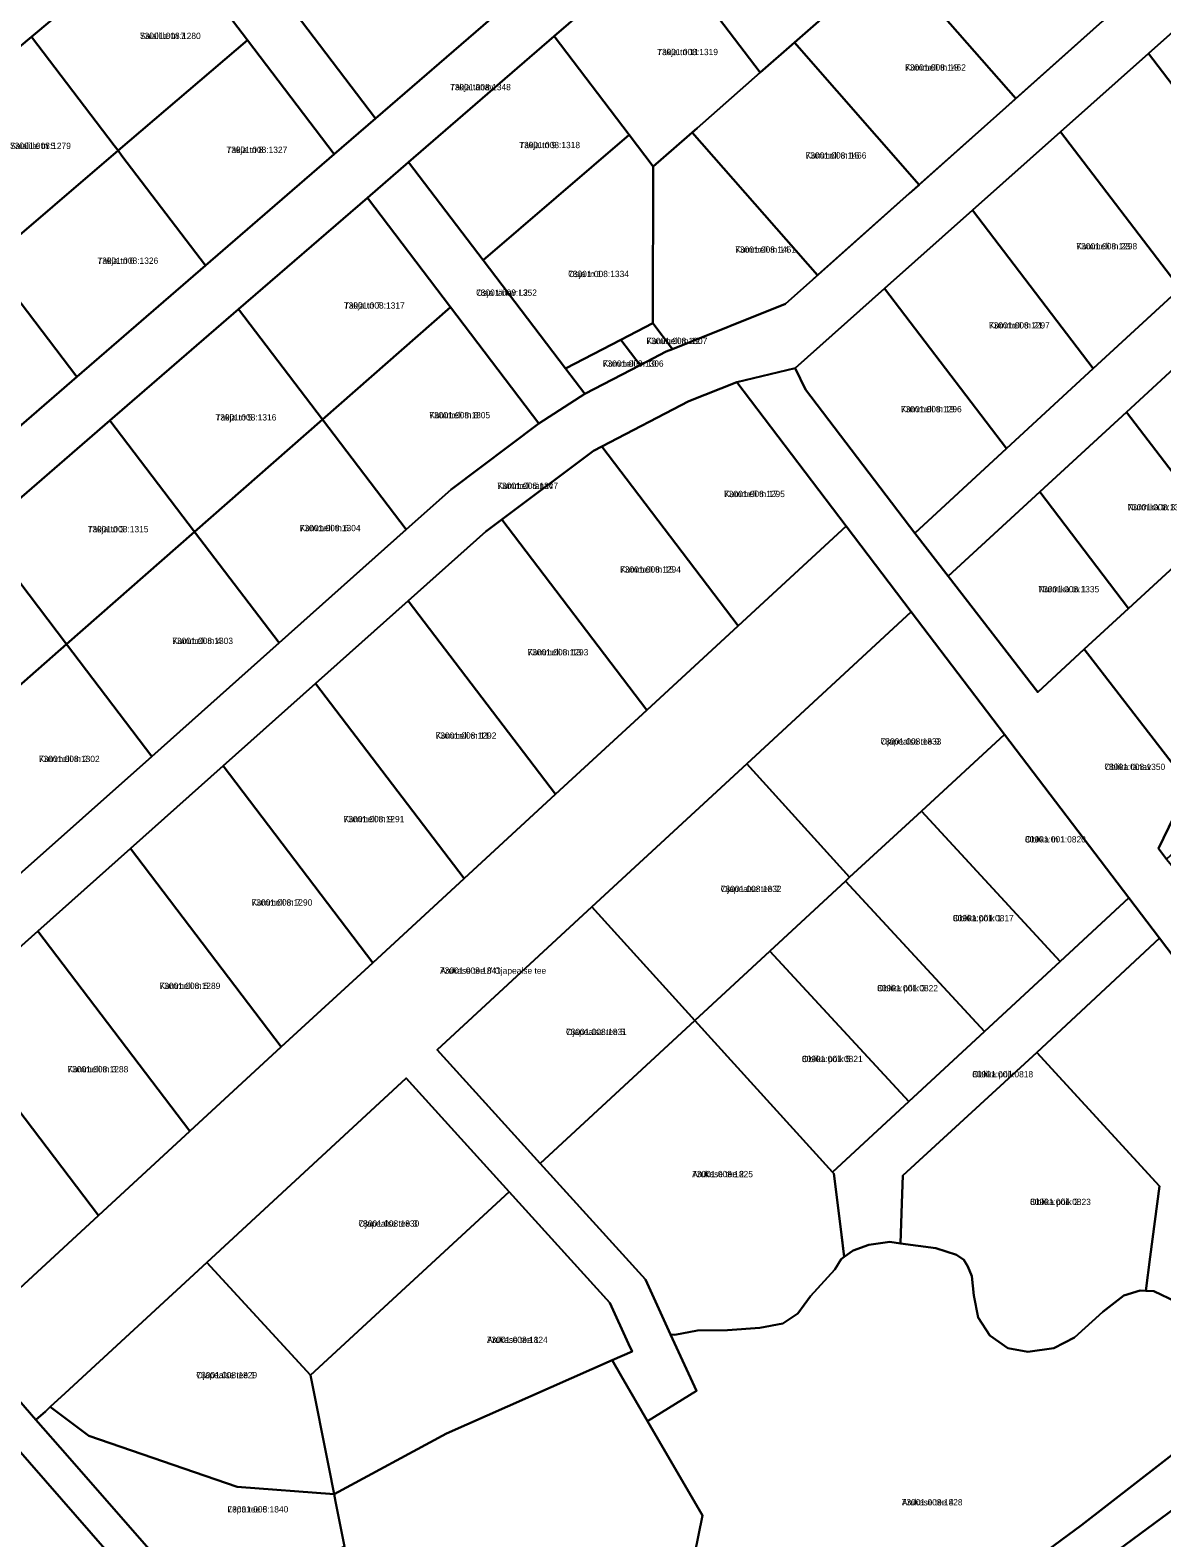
# Model space of a CAD drawing. Extents: x 524000 to 564260, y 6469338 to 6496391.
# Drawn here: x 535130.7 to 535400.5, y 6472024.8 to 6472384.2 of the extents above; entities that cross this region are included whole.
import ezdxf

# ---------------------------------------------------------------- set-up
doc = ezdxf.new("R2010")
doc.units = 0
for name, color, linetype in [('L_AADRESS', 7, 'Continuous'), ('PIIR', 7, 'Continuous'), ('TUNNUS', 7, 'Continuous')]:
    doc.layers.add(name, color=color, linetype=linetype)

msp = doc.modelspace()

# ---------------------------------------------------------------- linework, layer by layer
at = {"layer": 'PIIR'}
for points in [[(535113.22, 6472384.72), (535140.09, 6472407.24), (535166.96, 6472429.76), (535193.81, 6472452.26), (535220.65, 6472474.76), (535247.5, 6472497.26), (535274.37, 6472519.79), (535301.22, 6472542.29), (535326.58, 6472563.55), (535328.07, 6472564.8), (535335.94, 6472554.46), (535334.43, 6472553.19), (535308.7, 6472531.62), (535281.47, 6472508.79), (535254.23, 6472485.96), (535227, 6472463.13), (535199.76, 6472440.29), (535172.02, 6472417.04), (535162.04, 6472408.68), (535130.96, 6472382.62), (535099.89, 6472356.58)], [(535111.09, 6472274.99), (535141.78, 6472301.52), (535172.48, 6472328.06), (535203.18, 6472354.6), (535213.03, 6472363.12), (535240.43, 6472386.81), (535267.35, 6472410.08), (535294.25, 6472433.34), (535321.16, 6472456.61), (535348.06, 6472479.87), (535373.41, 6472501.79), (535374.98, 6472503.14), (535382.87, 6472492.75), (535381.32, 6472491.41), (535357.47, 6472470.79), (535332.08, 6472448.84), (535306.68, 6472426.89), (535281.29, 6472404.93), (535255.59, 6472382.72), (535220.92, 6472352.74), (535211.07, 6472344.22), (535180.37, 6472317.68), (535149.67, 6472291.14), (535118.97, 6472264.6)], [(535418.29, 6472397.33), (535397.32, 6472378.65), (535376.36, 6472359.97), (535355.39, 6472341.29), (535334.42, 6472322.61), (535313.08, 6472303.59), (535299.14, 6472300.3), (535287.77, 6472295.76), (535266.99, 6472284.97), (535264.96, 6472283.92), (535243.16, 6472267.54), (535239.34, 6472264.68), (535220.83, 6472248.19), (535198.74, 6472228.5), (535176.65, 6472208.82), (535154.56, 6472189.13), (535132.47, 6472169.45), (535110.37, 6472149.76)], [(535126.6, 6472181.63), (535159.68, 6472211.1), (535190.01, 6472238.12), (535220.33, 6472265.14), (535231.06, 6472274.71), (535251.99, 6472290.43), (535262.93, 6472297.51), (535276.1, 6472304.34), (535282.35, 6472307.59), (535283.86, 6472308.19), (535310.79, 6472318.97), (535317.21, 6472324.69), (535340.28, 6472345.24), (535363.35, 6472365.79), (535386.41, 6472386.34)], [(535115.53, 6472072.75), (535146.96, 6472101.69), (535168.76, 6472121.76), (535190.55, 6472141.83), (535212.34, 6472161.91), (535234.14, 6472181.99), (535255.93, 6472202.06), (535277.72, 6472222.14), (535299.52, 6472242.22), (535325.27, 6472265.94), (535340.78, 6472245.55), (535301.53, 6472209.33), (535264.61, 6472175.25), (535227.69, 6472141.17), (535252.24, 6472114.09), (535277.37, 6472086.38), (535283.37, 6472073.31), (535289.52, 6472059.91), (535277.89, 6472052.62), (535271.58, 6472063.44), (535269.41, 6472067.16), (535274.21, 6472069.28), (535273.38, 6472071.09), (535268.92, 6472080.81), (535244.89, 6472107.31), (535220.34, 6472134.39), (535172.76, 6472090.47), (535139.01, 6472059.32), (535135.47, 6472056.05), (535134.31, 6472054.98), (535132.04, 6472052.94), (535118.83, 6472068.12)], [(535298.79, 6471954.5), (535478.29, 6472086.95), (535613.88, 6472188.1), (535624.16, 6472196.1), (535638.82, 6472207.03)], [(535285.35, 6472002.41), (535291.02, 6472030.12), (535277.89, 6472052.62), (535289.52, 6472059.91), (535283.37, 6472073.31), (535284.36, 6472073.21), (535289.76, 6472074.27), (535296.97, 6472074.33), (535304.64, 6472074.88), (535310.14, 6472075.94), (535313.72, 6472078.29), (535316.72, 6472082.42), (535322.53, 6472088.76), (535324.03, 6472091.26), (535324.8, 6472091.83), (535326.89, 6472093.32), (535330.65, 6472094.67), (535335.69, 6472095.35), (535338.2, 6472095.02), (535346.67, 6472093.89), (535351.57, 6472092.26), (535353.32, 6472091.08), (535354.3, 6472089.52), (535355.2, 6472087.19), (535355.66, 6472082.59), (535356.7, 6472077.32), (535359.47, 6472073.09), (535363.77, 6472070.05), (535368.54, 6472069.19), (535374.75, 6472070.05), (535379.71, 6472072.57), (535386.46, 6472078.72), (535391.48, 6472082.56), (535395.32, 6472083.75), (535396.67, 6472083.7), (535398.63, 6472083.62), (535403.92, 6472081.11)], [(535412.98, 6472052.43), (535381.36, 6472027.86), (535302.63, 6471969.76)]]:
    msp.add_lwpolyline(points, dxfattribs=at)
for points in [[(535281.29, 6472404.93), (535306.68, 6472426.89), (535330, 6472396.23), (535312.9, 6472381.22), (535304.76, 6472374.07)], [(535336.11, 6472401.59), (535355.24, 6472418.39), (535359.31, 6472421.96), (535388.75, 6472388.43), (535386.41, 6472386.34), (535365.7, 6472367.89)], [(535203.18, 6472354.6), (535182.48, 6472381.81), (535162.04, 6472408.68), (535172.02, 6472417.04), (535192.07, 6472390.68), (535192.98, 6472389.48), (535193.89, 6472388.28), (535213.03, 6472363.12)], [(535192.98, 6472389.48), (535220.55, 6472412.95), (535221.46, 6472411.76), (535240.43, 6472386.81), (535213.03, 6472363.12), (535193.89, 6472388.28)], [(535130.96, 6472382.62), (535162.04, 6472408.68), (535182.48, 6472381.81), (535151.62, 6472355.47), (535150.71, 6472356.67)], [(535255.59, 6472382.72), (535281.29, 6472404.93), (535304.76, 6472374.07), (535289.7, 6472360.85), (535279.22, 6472351.65), (535273.48, 6472359.2)], [(535312.9, 6472381.22), (535330, 6472396.23), (535336.11, 6472401.59), (535365.7, 6472367.89), (535363.35, 6472365.79), (535342.64, 6472347.34)], [(535397.32, 6472378.65), (535418.29, 6472397.33), (535446.24, 6472360.71), (535425.56, 6472341.66)], [(535099.89, 6472356.58), (535130.96, 6472382.62), (535150.71, 6472356.67), (535151.62, 6472355.47), (535120.78, 6472329.12), (535119.86, 6472330.33)], [(535151.62, 6472355.47), (535182.48, 6472381.81), (535203.18, 6472354.6), (535172.48, 6472328.06), (535152.53, 6472354.27)], [(535220.92, 6472352.74), (535255.59, 6472382.72), (535273.48, 6472359.2), (535238.68, 6472329.4)], [(535288.5, 6472359.8), (535289.7, 6472360.85), (535304.76, 6472374.07), (535312.9, 6472381.22), (535342.64, 6472347.34), (535340.28, 6472345.24), (535318.4, 6472325.75)], [(535341.6, 6472264.32), (535363.5, 6472284.49), (535384.18, 6472303.54), (535404.88, 6472322.61), (535425.56, 6472341.66), (535446.24, 6472360.71), (535466.53, 6472379.4), (535468.03, 6472380.78), (535475.91, 6472370.37), (535474.45, 6472369.02), (535454.15, 6472350.33), (535433.47, 6472331.28), (535412.79, 6472312.23), (535392.1, 6472293.17), (535371.42, 6472274.12), (535349.61, 6472254.03)], [(535376.36, 6472359.97), (535397.32, 6472378.65), (535425.56, 6472341.66), (535404.88, 6472322.61)], [(535238.68, 6472329.4), (535273.48, 6472359.2), (535279.22, 6472351.65), (535279.16, 6472314.37), (535271.49, 6472310.4), (535258.32, 6472303.57)], [(535279.22, 6472351.65), (535288.5, 6472359.8), (535318.4, 6472325.75), (535317.21, 6472324.69), (535310.79, 6472318.97), (535283.86, 6472308.19), (535279.16, 6472314.37)], [(535355.39, 6472341.29), (535376.36, 6472359.97), (535404.88, 6472322.61), (535384.18, 6472303.54)], [(535120.78, 6472329.12), (535151.62, 6472355.47), (535152.53, 6472354.27), (535172.48, 6472328.06), (535141.78, 6472301.52), (535121.68, 6472327.93)], [(535251.99, 6472290.43), (535230.87, 6472318.2), (535211.07, 6472344.22), (535220.92, 6472352.74), (535238.68, 6472329.4), (535258.32, 6472303.57), (535262.93, 6472297.51)], [(535180.37, 6472317.68), (535211.07, 6472344.22), (535230.87, 6472318.2), (535200.35, 6472291.41)], [(535334.42, 6472322.61), (535355.39, 6472341.29), (535384.18, 6472303.54), (535363.5, 6472284.49)], [(535089.93, 6472302.79), (535120.78, 6472329.12), (535121.68, 6472327.93), (535141.78, 6472301.52), (535111.09, 6472274.99), (535090.84, 6472301.6)], [(535313.08, 6472303.59), (535334.42, 6472322.61), (535363.5, 6472284.49), (535341.6, 6472264.32), (535315.57, 6472298.54)], [(535149.67, 6472291.14), (535180.37, 6472317.68), (535200.35, 6472291.41), (535169.84, 6472264.63)], [(535200.35, 6472291.41), (535230.87, 6472318.2), (535251.99, 6472290.43), (535231.06, 6472274.71), (535220.33, 6472265.14)], [(535271.49, 6472310.4), (535279.16, 6472314.37), (535283.86, 6472308.19), (535282.35, 6472307.59), (535276.1, 6472304.34)], [(535392.1, 6472293.17), (535412.79, 6472312.23), (535433.97, 6472284.48), (535413.29, 6472265.39)], [(535258.32, 6472303.57), (535271.49, 6472310.4), (535276.1, 6472304.34), (535262.93, 6472297.51)], [(535266.99, 6472284.97), (535287.77, 6472295.76), (535299.14, 6472300.3), (535325.27, 6472265.94), (535299.52, 6472242.22)], [(535362.97, 6472216.3), (535340.78, 6472245.55), (535325.27, 6472265.94), (535299.14, 6472300.3), (535313.08, 6472303.59), (535315.57, 6472298.54), (535341.6, 6472264.32), (535349.61, 6472254.03), (535370.94, 6472226.42), (535382.02, 6472236.62), (535407.04, 6472204.23), (535399.76, 6472189.17), (535401.66, 6472186.63), (535402.87, 6472185.09), (535412.32, 6472172.76), (535432.95, 6472145.9), (535452.15, 6472120.89), (535442.26, 6472112.1), (535399.94, 6472167.74), (535392.62, 6472177.34)], [(535371.42, 6472274.12), (535392.1, 6472293.17), (535413.29, 6472265.39), (535392.58, 6472246.36)], [(535118.97, 6472264.6), (535149.67, 6472291.14), (535169.84, 6472264.63), (535139.33, 6472237.85)], [(535169.84, 6472264.63), (535200.35, 6472291.41), (535220.33, 6472265.14), (535190.01, 6472238.12)], [(535243.16, 6472267.54), (535264.96, 6472283.92), (535266.99, 6472284.97), (535299.52, 6472242.22), (535277.72, 6472222.14)], [(535433.97, 6472284.48), (535464.51, 6472244.43), (535401.66, 6472186.63), (535399.76, 6472189.17), (535407.04, 6472204.23), (535382.02, 6472236.62), (535392.58, 6472246.36), (535413.29, 6472265.39)], [(535349.61, 6472254.03), (535371.42, 6472274.12), (535392.58, 6472246.36), (535382.02, 6472236.62), (535370.94, 6472226.42)], [(535086.57, 6472236.59), (535118.97, 6472264.6), (535139.33, 6472237.85), (535106.58, 6472209.11)], [(535139.33, 6472237.85), (535169.84, 6472264.63), (535190.01, 6472238.12), (535159.68, 6472211.1)], [(535220.83, 6472248.19), (535239.34, 6472264.68), (535243.16, 6472267.54), (535277.72, 6472222.14), (535255.93, 6472202.06)], [(535198.74, 6472228.5), (535220.83, 6472248.19), (535255.93, 6472202.06), (535234.14, 6472181.99)], [(535301.53, 6472209.33), (535340.78, 6472245.55), (535362.97, 6472216.3), (535343.19, 6472198.03), (535326.04, 6472182.27)], [(535106.58, 6472209.11), (535139.33, 6472237.85), (535159.68, 6472211.1), (535126.6, 6472181.63)], [(535176.65, 6472208.82), (535198.74, 6472228.5), (535234.14, 6472181.99), (535212.34, 6472161.91)], [(535376.32, 6472162.22), (535343.19, 6472198.03), (535362.97, 6472216.3), (535392.62, 6472177.34)], [(535154.56, 6472189.13), (535176.65, 6472208.82), (535212.34, 6472161.91), (535190.55, 6472141.83)], [(535307.05, 6472164.67), (535289.18, 6472148.17), (535264.61, 6472175.25), (535301.53, 6472209.33), (535326.04, 6472182.27), (535325.1, 6472181.37)], [(535358.25, 6472145.52), (535325.1, 6472181.37), (535326.04, 6472182.27), (535343.19, 6472198.03), (535376.32, 6472162.22)], [(535132.47, 6472169.45), (535154.56, 6472189.13), (535190.55, 6472141.83), (535168.76, 6472121.76)], [(535340.2, 6472128.83), (535307.05, 6472164.67), (535325.1, 6472181.37), (535358.25, 6472145.52)], [(535227.69, 6472141.17), (535264.61, 6472175.25), (535289.18, 6472148.17), (535252.24, 6472114.09)], [(535322.28, 6472111.65), (535321.99, 6472111.99), (535340.2, 6472128.83), (535358.25, 6472145.52), (535376.32, 6472162.22), (535392.62, 6472177.34), (535399.94, 6472167.74), (535370.68, 6472140.51), (535338.8, 6472111.19), (535338.55, 6472104.59), (535338.2, 6472095.02), (535335.69, 6472095.35), (535330.65, 6472094.67), (535326.89, 6472093.32), (535324.8, 6472091.83), (535323.8, 6472099.68)], [(535110.37, 6472149.76), (535132.47, 6472169.45), (535168.76, 6472121.76), (535146.96, 6472101.69)], [(535400, 6472108.63), (535370.68, 6472140.51), (535399.94, 6472167.74), (535442.26, 6472112.1), (535455.45, 6472094.81), (535445.91, 6472087.3), (535428.99, 6472069.36), (535423.36, 6472063.39), (535420.71, 6472065.2), (535419.77, 6472066.01), (535415.41, 6472069.78), (535409.37, 6472077.69), (535403.92, 6472081.11), (535398.63, 6472083.62), (535396.67, 6472083.7), (535397.75, 6472091.8)], [(535321.99, 6472111.99), (535289.18, 6472148.17), (535307.05, 6472164.67), (535340.2, 6472128.83)], [(535079.48, 6472122.23), (535110.37, 6472149.76), (535146.96, 6472101.69), (535115.53, 6472072.75), (535103.74, 6472088.93)], [(535322.53, 6472088.76), (535316.72, 6472082.42), (535313.72, 6472078.29), (535310.14, 6472075.94), (535304.64, 6472074.88), (535296.97, 6472074.33), (535289.76, 6472074.27), (535284.36, 6472073.21), (535283.37, 6472073.31), (535277.37, 6472086.38), (535252.24, 6472114.09), (535289.18, 6472148.17), (535321.99, 6472111.99), (535322.28, 6472111.65), (535324.14, 6472097.15), (535324.8, 6472091.83), (535324.03, 6472091.26)], [(535338.55, 6472104.59), (535338.8, 6472111.19), (535370.68, 6472140.51), (535400, 6472108.63), (535397.75, 6472091.8), (535396.67, 6472083.7), (535395.32, 6472083.75), (535391.48, 6472082.56), (535386.46, 6472078.72), (535379.72, 6472072.57), (535374.75, 6472070.05), (535368.54, 6472069.19), (535363.77, 6472070.05), (535359.47, 6472073.09), (535356.7, 6472077.32), (535355.66, 6472082.59), (535355.2, 6472087.19), (535354.3, 6472089.52), (535353.32, 6472091.08), (535351.57, 6472092.26), (535346.67, 6472093.89), (535338.2, 6472095.02)], [(535172.76, 6472090.47), (535220.34, 6472134.39), (535244.89, 6472107.31), (535197.55, 6472063.61)], [(535201.9, 6472041.64), (535197.55, 6472063.61), (535244.89, 6472107.31), (535268.92, 6472080.81), (535273.38, 6472071.09), (535274.21, 6472069.28), (535269.41, 6472067.16), (535229.95, 6472049.72), (535203.16, 6472035.27)], [(535264.68, 6471941.76), (535285.62, 6471957.21), (535302.63, 6471969.76), (535381.36, 6472027.86), (535412.98, 6472052.43), (535417.85, 6472057.58), (535423.36, 6472063.39), (535428.99, 6472069.36), (535445.91, 6472087.3), (535455.45, 6472094.81), (535465.93, 6472103.05), (535469.22, 6472098.73), (535478.29, 6472086.95), (535298.79, 6471954.5), (535270.76, 6471933.77)], [(535135.47, 6472056.05), (535139.01, 6472059.32), (535172.76, 6472090.47), (535197.55, 6472063.61), (535201.9, 6472041.64), (535203.16, 6472035.27), (535180.04, 6472037.01), (535144.69, 6472049.11)], [(535243.25, 6471913.67), (535112.43, 6472063.39), (535118.83, 6472068.12), (535132.04, 6472052.94), (535139.6, 6472044.38), (535173.44, 6472005.7), (535179.55, 6471998.7), (535249.66, 6471918.38)], [(535269.41, 6472067.16), (535271.58, 6472063.44), (535277.89, 6472052.62), (535291.02, 6472030.12), (535285.35, 6472002.41), (535236.46, 6471978.82), (535233.36, 6471976.85), (535204.08, 6472012.54), (535179.55, 6471998.7), (535173.44, 6472005.7), (535205.58, 6472022.79), (535203.5, 6472033.51), (535203.16, 6472035.27), (535229.95, 6472049.72)], [(535066.56, 6471943.12), (535021.96, 6471996.63), (535053.4, 6472019.82), (535110.84, 6472062.22), (535112.43, 6472063.39), (535243.25, 6471913.67), (535148.85, 6471844.29), (535125.57, 6471872.24), (535101.66, 6471900.94)], [(535132.04, 6472052.94), (535134.31, 6472054.98), (535135.47, 6472056.05), (535144.69, 6472049.11), (535180.04, 6472037.01), (535203.16, 6472035.27), (535203.5, 6472033.51), (535205.58, 6472022.79), (535173.44, 6472005.7), (535139.6, 6472044.38)]]:
    msp.add_lwpolyline(points, close=True, dxfattribs=at)

# ---------------------------------------------------------------- texts
at = {"layer": 'L_AADRESS'}
for s, p in [('Saialille tn 7', (535156.83, 6472382.07)), ('Takja tn 11', (535280.18, 6472378.23)), ('Kummeli tn 18', (535339.3, 6472374.55)), ('Takja tänav', (535230.78, 6472369.87)), ('Saialille tn 5', (535125.87, 6472355.87)), ('Takja tn 8', (535177.48, 6472354.93)), ('Takja tn 9', (535247.29, 6472356.06)), ('Kummeli tn 16', (535315.57, 6472353.58)), ('Kummeli tn 14', (535298.78, 6472331.13)), ('Kummeli tn 23', (535380.14, 6472331.93)), ('Takja tn 6', (535146.7, 6472328.49)), ('Osja tn 1', (535258.95, 6472325.33)), ('Osja tänav L2', (535237, 6472320.87)), ('Takja tn 7', (535205.48, 6472317.82)), ('Kummeli tn 21', (535359.3, 6472313.08)), ('Kummeli tn 12', (535277.63, 6472309.36)), ('Kummeli tn 10', (535267.21, 6472303.96)), ('Kummeli tn 8', (535225.85, 6472291.67)), ('Kummeli tn 19', (535338.29, 6472293.1)), ('Takja tn 5', (535174.87, 6472291.15)), ('Kummeli tänav', (535242.05, 6472274.84)), ('Kummeli tn 17', (535296.13, 6472272.89)), ('Nurmika tn 3', (535392.36, 6472269.75)), ('Takja tn 3', (535144.37, 6472264.5)), ('Kummeli tn 6', (535194.95, 6472264.77)), ('Kummeli tn 15', (535271.34, 6472254.89)), ('Nurmika tn 1', (535371.09, 6472250.19)), ('Kummeli tn 4', (535164.54, 6472237.87)), ('Kummeli tn 13', (535249.27, 6472235.16)), ('Kummeli tn 11', (535227.34, 6472215.29)), ('Ojapealse tee 9', (535333.44, 6472213.91)), ('Kummeli tn 2', (535132.73, 6472209.74)), ('Oblika tänav', (535386.83, 6472207.85)), ('Kummeli tn 9', (535205.39, 6472195.4)), ('Oblika tn 1', (535367.9, 6472190.57)), ('Ojapealse tee 7', (535295.33, 6472178.75)), ('Kummeli tn 7', (535183.45, 6472175.52)), ('Oblika põik 1', (535350.71, 6472171.79)), ('Arukase tee // Ojapealse tee', (535228.4, 6472159.28)), ('Kummeli tn 5', (535161.51, 6472155.64)), ('Oblika põik 3', (535332.65, 6472155.1)), ('Ojapealse tee 5', (535258.43, 6472144.67)), ('Oblika põik 5', (535314.69, 6472138.22)), ('Kummeli tn 3', (535139.56, 6472135.77)), ('Oblika põik', (535355.33, 6472134.58)), ('Arukase tee 2', (535288.52, 6472110.79)), ('Oblika põik 2', (535369.1, 6472104.16)), ('Ojapealse tee 3', (535208.94, 6472099)), ('Arukase tee 1', (535239.58, 6472071.29)), ('Ojapealse tee 1', (535170.28, 6472062.87)), ('Lepa tee 5', (535177.71, 6472030.88)), ('Arukase tee 4', (535338.5, 6472032.56))]:
    msp.add_text(s, height=1.5, dxfattribs=at).set_placement(p)
at = {"layer": 'TUNNUS'}
for s, p in [('73001:008:1280', (535156.83, 6472382.07)), ('73001:008:1319', (535280.18, 6472378.23)), ('73001:008:1462', (535339.3, 6472374.55)), ('73001:008:1348', (535230.78, 6472369.87)), ('73001:008:1279', (535125.87, 6472355.87)), ('73001:008:1327', (535177.48, 6472354.93)), ('73001:008:1318', (535247.29, 6472356.06)), ('73001:008:1466', (535315.57, 6472353.58)), ('73001:008:1461', (535298.78, 6472331.13)), ('73001:008:1298', (535380.14, 6472331.93)), ('73001:008:1326', (535146.7, 6472328.49)), ('73001:008:1334', (535258.95, 6472325.33)), ('73001:008:1352', (535237, 6472320.87)), ('73001:008:1317', (535205.48, 6472317.82)), ('73001:008:1297', (535359.3, 6472313.08)), ('73001:008:1307', (535277.63, 6472309.36)), ('73001:008:1306', (535267.21, 6472303.96)), ('73001:008:1305', (535225.85, 6472291.67)), ('73001:008:1296', (535338.29, 6472293.1)), ('73001:008:1316', (535174.87, 6472291.15)), ('73001:008:1347', (535242.05, 6472274.84)), ('73001:008:1295', (535296.13, 6472272.89)), ('73001:008:1336', (535392.36, 6472269.75)), ('73001:008:1315', (535144.37, 6472264.5)), ('73001:008:1304', (535194.95, 6472264.77)), ('73001:008:1294', (535271.34, 6472254.89)), ('73001:008:1335', (535371.09, 6472250.19)), ('73001:008:1303', (535164.54, 6472237.87)), ('73001:008:1293', (535249.27, 6472235.16)), ('73001:008:1292', (535227.34, 6472215.29)), ('73001:008:1833', (535333.44, 6472213.91)), ('73001:008:1302', (535132.73, 6472209.74)), ('73001:008:1350', (535386.83, 6472207.85)), ('73001:008:1291', (535205.39, 6472195.4)), ('80901:001:0820', (535367.9, 6472190.57)), ('73001:008:1832', (535295.33, 6472178.75)), ('73001:008:1290', (535183.45, 6472175.52)), ('80901:001:0817', (535350.71, 6472171.79)), ('73001:008:1841', (535228.4, 6472159.28)), ('73001:008:1289', (535161.51, 6472155.64)), ('80901:001:0822', (535332.65, 6472155.1)), ('73001:008:1831', (535258.43, 6472144.67)), ('80901:001:0821', (535314.69, 6472138.22)), ('73001:008:1288', (535139.56, 6472135.77)), ('80901:001:0818', (535355.33, 6472134.58)), ('73001:008:1825', (535288.52, 6472110.79)), ('80901:001:0823', (535369.1, 6472104.16)), ('73001:008:1830', (535208.94, 6472099)), ('73001:008:1824', (535239.58, 6472071.29)), ('73001:008:1829', (535170.28, 6472062.87)), ('73001:008:1840', (535177.71, 6472030.88)), ('73001:008:1828', (535338.5, 6472032.56))]:
    msp.add_text(s, height=1.5, dxfattribs=at).set_placement(p)

doc.saveas('drawing.dxf')
